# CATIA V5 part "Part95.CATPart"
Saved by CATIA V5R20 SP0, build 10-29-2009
Part number: FA 063200-1
Revision: ANY
Definition: UNKNOWN
Nomenclature: FA 063200-1
Source: Unknown
Bounding box of the stored display mesh (mm): x -2.5 to 2.5, y 0.15 to 2.5, z -2.5 to 2.5
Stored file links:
  C:\Users\Utente\Desktop\IO LAVORO\3D X SITO CF\CUMSA\3D files FA\FA 063200\Part95.CATPart

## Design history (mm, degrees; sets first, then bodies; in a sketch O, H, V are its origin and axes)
Body1 "Cortar-Extruir1" (main body)
  Solid1: solid without history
